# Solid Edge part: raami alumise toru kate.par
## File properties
Title: raami alumise toru kate
Author: Stella-Marii
Template: iso metric part.par
Last saved by: Stella-Marii
Revision: 12
Application: Solid Edge
Document Number: 35
Density: 1024,000 kg/m^3
Accuracy: 0,990
Username: Stella-Marii
Material: ABS Plastic, high impact
Face Style: Red
Fill Style: ANSI34(Plastic)
Virtual Style: Red (Shiny)
Grouping: Non-metals\Plastics
LibraryName: Materials
Coef. of Thermal Exp: 9e-05
Thermal Conductivity: 0.2
Specific Heat: 0.0
Modulus of Elasticity: 1378951400.0
Poisson's Ratio: 0.4
Yield Stress: 31026406.5
Ultimate Stress: 0.0
Elongation: 0.0
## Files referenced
..\scooter.asm
@C:\Users\Stella-Marii\DATA\KOOL\Solid Edge - scooter\scooter.asm
C:\Users\Stella-Marii\DATA\KOOL\Solid Edge - scooter\laadimisjupp.par
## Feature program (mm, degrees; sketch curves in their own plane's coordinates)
sketch for "unnamed Protrusion 1" plane through (0, 0, 0) normal (0, 0, 1) x-axis (1, 0, 0)
  circle centre (0, 0) radius 25.5
extrude "unnamed Protrusion 1" add finite 50 along +normal
sketch for "ExtrudedCutout_1" plane through (0, 0, 0) normal (1, 0, 0) x-axis (0, 1, 0)
  line (-25.5, 0) -> (-25.5, 26.2183)
  line (-25.5, 26.2183) -> (25.5, 50)
  line (25.5, 50) -> (25.5, 23.7817)
  line (25.5, 23.7817) -> (-25.5, 0)
extrude "ExtrudedCutout_1" cut finite 75.2511 symmetric
thinwall "Thinwall_1"  Thickness = 3 mm
sketch for "ExtrudedCutout_2" plane through (0, 0, 0) normal (0, 0, 1) x-axis (1, 0, 0)
extrude "ExtrudedCutout_2" cut finite 18.566 along +normal
sketch for "ExtrudedCutout_3" plane through (0, 0, 0) normal (0, 0, 1) x-axis (1, 0, 0)
extrude "ExtrudedCutout_3" cut finite 119.8821 symmetric
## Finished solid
Body 1: solid body, 10 faces, 24 edges, 16 vertices.
  Faces by surface: plane 6, cylinder 4
  Edges by curve: line 12, ellipse 10, circle 2
Bounding box of the edges (mm): 51.000 x 45.946 x 47.643, from (-25.5, -25.5, 0) to (25.5, 20.4459, 47.6433).
Cylindrical faces by radius (mm): R22.5 x2, R24 x1, R25.5 x1
Planar faces by outward normal: -y 2, -z 1, oblique 3
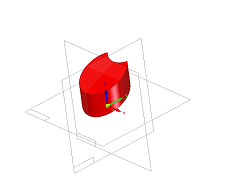
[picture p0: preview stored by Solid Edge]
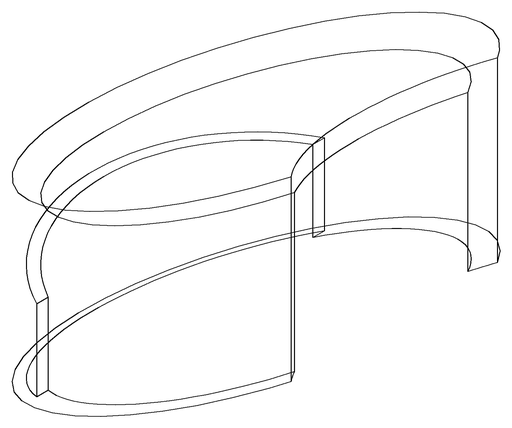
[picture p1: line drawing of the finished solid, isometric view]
